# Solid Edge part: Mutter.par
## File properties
Sűrűség: 0,000 kg/m^3
Pontosság: 0,990
Author: ahadarics
Last saved by: psaghy
Revision: 77
Username: ahadarics
Dokumentum tartalom típus: 0
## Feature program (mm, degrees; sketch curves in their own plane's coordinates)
base feature "unnamed BaseFeature 1"
sketch for "Furat_1" plane through (0, 0, 0) normal (-1, 0, 0) x-axis (0, -1, 0)
  hole centre (0, 0) bore radius 16.9175
hole "Furat_1" through  StartChamferOffset = 0.92 mm; StartChamferAngle = 45 deg
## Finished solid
Body 1: solid body, 23 faces, 47 edges, 26 vertices.
  Faces by surface: cone 14, plane 8, cylinder 1
  Edges by curve: spline 24, circle 16, line 7
Bounding box of the edges (mm): 14.000 x 63.508 x 55.000, from (0, -31.7543, -27.5) to (14, 31.7543, 27.5).
Cylindrical faces by radius (mm): R16.9175 x1
Conical faces (half-angle, radius in mm at the cone's reference point): 45 deg R17.8375 x1, 60 deg R17.1881 x1, 60 deg R29.6271 x12
Planar faces by outward normal: +x 1, +z 1, -x 1, -z 1, oblique 4
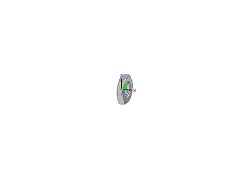
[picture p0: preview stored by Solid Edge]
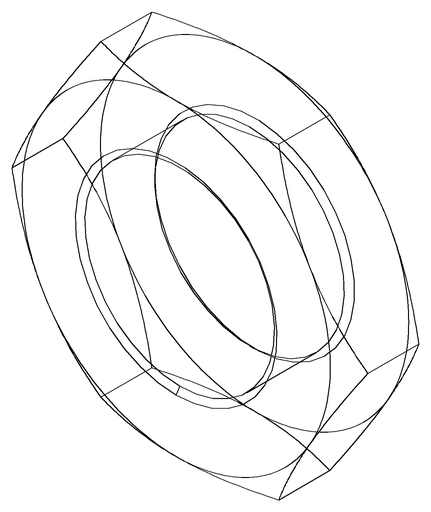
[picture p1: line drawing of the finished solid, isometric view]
